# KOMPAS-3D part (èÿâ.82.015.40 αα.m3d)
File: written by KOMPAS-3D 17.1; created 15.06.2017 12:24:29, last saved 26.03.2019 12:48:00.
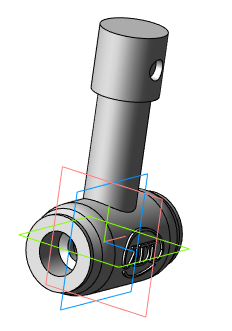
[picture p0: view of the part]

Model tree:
1. Операция без истории:2  (labels: Сталь 20  ГОСТ 1050-88)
